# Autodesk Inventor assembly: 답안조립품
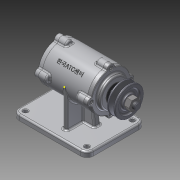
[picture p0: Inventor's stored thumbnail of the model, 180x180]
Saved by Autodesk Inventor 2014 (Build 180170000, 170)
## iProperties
Created: 2015-12
Part Number: 답안조립품
Document SubType Name: Assembly
Designer: user
Author: user
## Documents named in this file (11)
- C:\Users\user\Desktop\451208V1027\답안조립품.iam
- C:\Users\user\Desktop\451208V1027\본체.ipt
- C:\Users\user\Desktop\451208V1027\커버.ipt
- C:\Users\user\Desktop\451208V1027\축.ipt
- C:\Users\user\Desktop\451208V1027\키(4 x 4 x 12).ipt
- C:\Users\user\Desktop\451208V1027\V-벨트풀리.ipt
- C:\Users\user\Desktop\451208V1027\베어링 6204.ipt
- C:\Users\user\Desktop\451208V1027\너트 M12x1.25.ipt
- C:\Users\user\Desktop\451208V1027\커버2.ipt
- C:\Users\user\Desktop\451208V1027\볼트 M4 x 12.ipt
- C:\Users\user\Desktop\451208V1027\오일실.ipt
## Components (6 placed, 5 different names)
1. KS B 1311 (I) 4 x 4 x 12:1 — Insert:1, Mate:1, Angle:1
2. V-벨트풀리:1 — Insert:2, Angle:1, Insert:7
3. KS B 2023 6204 - 20 x 47 x 14:1 — Insert:4, Insert:5
4. KS B 2023 6204 - 20 x 47 x 14:2 — Insert:3
5. KS B 1012 클래스 1 일반 - 미터 M12x1.25:1 — Insert:7, Mate:3
6. KS B 2804 D D - 20 32 8:1 — Insert:11
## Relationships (10: Insert 7, Mate 2, Angle 1)
- Insert:1: KS B 1311 (I) 4 x 4 x 12:1
- Mate:1: KS B 1311 (I) 4 x 4 x 12:1
- Insert:2: V-벨트풀리:1
- Angle:1: KS B 1311 (I) 4 x 4 x 12:1 ↔ V-벨트풀리:1
- Insert:3: KS B 2023 6204 - 20 x 47 x 14:2
- Insert:4: KS B 2023 6204 - 20 x 47 x 14:1
- Insert:5: KS B 2023 6204 - 20 x 47 x 14:1
- Insert:7: V-벨트풀리:1 ↔ KS B 1012 클래스 1 일반 - 미터 M12x1.25:1
- Insert:11: KS B 2804 D D - 20 32 8:1
- Mate:3: KS B 1012 클래스 1 일반 - 미터 M12x1.25:1
